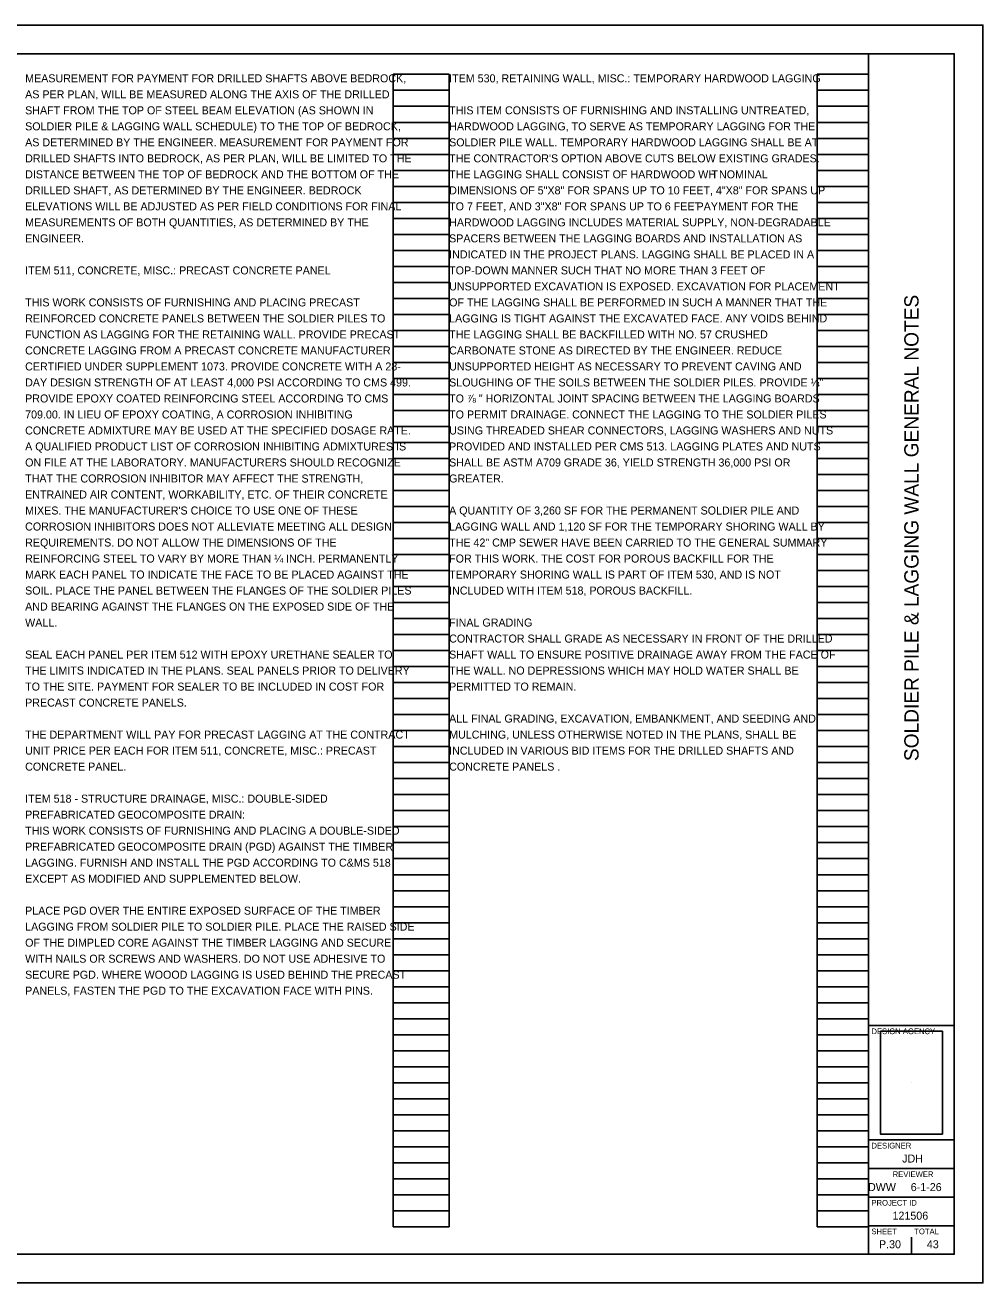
# Model space of a CAD drawing. Extents: x 0 to 34, y 0 to 22.
# Drawn here: x 17.24 to 34, y 0 to 22 of the extents above; entities that cross this region are included whole.
import ezdxf

# ---------------------------------------------------------------- set-up
doc = ezdxf.new("R2010")
doc.units = 0
for name, color, linetype in [('Default', 7, 'Continuous'), ('SH_Border', 7, 'Continuous'), ('SH_Cut_Line', 7, 'Continuous'), ('SH_Data', 7, 'Continuous'), ('SH_Text', 7, 'Continuous')]:
    doc.layers.add(name, color=color, linetype=linetype)

msp = doc.modelspace()

# ---------------------------------------------------------------- linework, layer by layer
at = {"layer": 'SH_Border'}
for p, q in [((32, 0.5), (32, 21.5)), ((32, 4.5), (33.5, 4.5)), ((32, 2.5), (33.5, 2.5)), ((32, 2), (33.5, 2)), ((32, 1.5), (33.5, 1.5)), ((32, 1), (33.5, 1))]:
    msp.add_line(p, q, dxfattribs=at)
msp.add_lwpolyline([(1.5, 21.5), (33.5, 21.5), (33.5, 0.5), (1.5, 0.5)], close=True, dxfattribs=at)
at = {"layer": 'SH_Cut_Line'}
msp.add_lwpolyline([(0, 0), (34, 0), (34, 22), (0, 22)], close=True, dxfattribs=at)
at = {"layer": 'SH_Data'}
for p, q in [((23.68, 0.98), (23.68, 21.14)), ((23.68, 21.14), (24.66, 21.14)), ((24.66, 0.98), (24.66, 21.14)), ((31.1, 0.98), (31.1, 21.14)), ((31.1, 21.14), (32, 21.14)), ((32, 0.98), (32, 21.14)), ((23.68, 20.86), (24.66, 20.86)), ((31.1, 20.86), (32, 20.86)), ((23.68, 20.58), (24.66, 20.58)), ((31.1, 20.58), (32, 20.58)), ((23.68, 20.3), (24.66, 20.3)), ((31.1, 20.3), (32, 20.3)), ((23.68, 20.02), (24.66, 20.02)), ((31.1, 20.02), (32, 20.02)), ((23.68, 19.74), (24.66, 19.74)), ((31.1, 19.74), (32, 19.74)), ((23.68, 19.46), (24.66, 19.46)), ((31.1, 19.46), (32, 19.46)), ((23.68, 19.18), (24.66, 19.18)), ((31.1, 19.18), (32, 19.18)), ((23.68, 18.9), (24.66, 18.9)), ((31.1, 18.9), (32, 18.9)), ((23.68, 18.62), (24.66, 18.62)), ((31.1, 18.62), (32, 18.62)), ((23.68, 18.34), (24.66, 18.34)), ((31.1, 18.34), (32, 18.34)), ((23.68, 18.06), (24.66, 18.06)), ((31.1, 18.06), (32, 18.06)), ((23.68, 17.78), (24.66, 17.78)), ((31.1, 17.78), (32, 17.78)), ((23.68, 17.5), (24.66, 17.5)), ((31.1, 17.5), (32, 17.5)), ((23.68, 17.22), (24.66, 17.22)), ((31.1, 17.22), (32, 17.22)), ((23.68, 16.94), (24.66, 16.94)), ((31.1, 16.94), (32, 16.94)), ((23.68, 16.66), (24.66, 16.66)), ((31.1, 16.66), (32, 16.66)), ((23.68, 16.38), (24.66, 16.38)), ((31.1, 16.38), (32, 16.38)), ((23.68, 16.1), (24.66, 16.1)), ((31.1, 16.1), (32, 16.1)), ((23.68, 15.82), (24.66, 15.82)), ((31.1, 15.82), (32, 15.82)), ((23.68, 15.54), (24.66, 15.54)), ((31.1, 15.54), (32, 15.54)), ((23.68, 15.26), (24.66, 15.26)), ((31.1, 15.26), (32, 15.26)), ((23.68, 14.98), (24.66, 14.98)), ((31.1, 14.98), (32, 14.98)), ((23.68, 14.7), (24.66, 14.7)), ((31.1, 14.7), (32, 14.7)), ((23.68, 14.42), (24.66, 14.42)), ((31.1, 14.42), (32, 14.42)), ((23.68, 14.14), (24.66, 14.14)), ((31.1, 14.14), (32, 14.14)), ((23.68, 13.86), (24.66, 13.86)), ((31.1, 13.86), (32, 13.86)), ((23.68, 13.58), (24.66, 13.58)), ((31.1, 13.58), (32, 13.58)), ((23.68, 13.3), (24.66, 13.3)), ((31.1, 13.3), (32, 13.3)), ((23.68, 13.02), (24.66, 13.02)), ((31.1, 13.02), (32, 13.02)), ((23.68, 12.74), (24.66, 12.74)), ((31.1, 12.74), (32, 12.74)), ((23.68, 12.46), (24.66, 12.46)), ((31.1, 12.46), (32, 12.46)), ((23.68, 12.18), (24.66, 12.18)), ((31.1, 12.18), (32, 12.18)), ((23.68, 11.9), (24.66, 11.9)), ((31.1, 11.9), (32, 11.9)), ((23.68, 11.62), (24.66, 11.62)), ((31.1, 11.62), (32, 11.62)), ((23.68, 11.34), (24.66, 11.34)), ((31.1, 11.34), (32, 11.34)), ((23.68, 11.06), (24.66, 11.06)), ((31.1, 11.06), (32, 11.06)), ((23.68, 10.78), (24.66, 10.78)), ((31.1, 10.78), (32, 10.78)), ((23.68, 10.5), (24.66, 10.5)), ((31.1, 10.5), (32, 10.5)), ((23.68, 10.22), (24.66, 10.22)), ((31.1, 10.22), (32, 10.22)), ((23.68, 9.94), (24.66, 9.94)), ((31.1, 9.94), (32, 9.94)), ((23.68, 9.66), (24.66, 9.66)), ((31.1, 9.66), (32, 9.66)), ((23.68, 9.38), (24.66, 9.38)), ((31.1, 9.38), (32, 9.38)), ((23.68, 9.1), (24.66, 9.1)), ((31.1, 9.1), (32, 9.1)), ((23.68, 8.82), (24.66, 8.82)), ((31.1, 8.82), (32, 8.82)), ((23.68, 8.54), (24.66, 8.54)), ((31.1, 8.54), (32, 8.54)), ((23.68, 8.26), (24.66, 8.26)), ((31.1, 8.26), (32, 8.26)), ((23.68, 7.98), (24.66, 7.98)), ((31.1, 7.98), (32, 7.98)), ((23.68, 7.7), (24.66, 7.7)), ((31.1, 7.7), (32, 7.7)), ((23.68, 7.42), (24.66, 7.42)), ((31.1, 7.42), (32, 7.42)), ((23.68, 7.14), (24.66, 7.14)), ((31.1, 7.14), (32, 7.14)), ((23.68, 6.86), (24.66, 6.86)), ((31.1, 6.86), (32, 6.86)), ((23.68, 6.58), (24.66, 6.58)), ((31.1, 6.58), (32, 6.58)), ((23.68, 6.3), (24.66, 6.3)), ((31.1, 6.3), (32, 6.3)), ((23.68, 6.02), (24.66, 6.02)), ((31.1, 6.02), (32, 6.02)), ((23.68, 5.74), (24.66, 5.74)), ((31.1, 5.74), (32, 5.74)), ((23.68, 5.46), (24.66, 5.46)), ((31.1, 5.46), (32, 5.46)), ((23.68, 5.18), (24.66, 5.18)), ((31.1, 5.18), (32, 5.18)), ((23.68, 4.9), (24.66, 4.9)), ((31.1, 4.9), (32, 4.9)), ((23.68, 4.62), (24.66, 4.62)), ((31.1, 4.62), (32, 4.62)), ((23.68, 4.34), (24.66, 4.34)), ((31.1, 4.34), (32, 4.34)), ((23.68, 4.06), (24.66, 4.06)), ((31.1, 4.06), (32, 4.06)), ((23.68, 3.78), (24.66, 3.78)), ((31.1, 3.78), (32, 3.78)), ((23.68, 3.5), (24.66, 3.5)), ((31.1, 3.5), (32, 3.5)), ((32.75, 3.5), (32.75, 3.5)), ((23.68, 3.22), (24.66, 3.22)), ((31.1, 3.22), (32, 3.22)), ((23.68, 2.94), (24.66, 2.94)), ((31.1, 2.94), (32, 2.94)), ((23.68, 2.66), (24.66, 2.66)), ((31.1, 2.66), (32, 2.66)), ((23.68, 2.38), (24.66, 2.38)), ((31.1, 2.38), (32, 2.38)), ((23.68, 2.1), (24.66, 2.1)), ((31.1, 2.1), (32, 2.1)), ((23.68, 1.82), (24.66, 1.82)), ((31.1, 1.82), (32, 1.82)), ((23.68, 1.54), (24.66, 1.54)), ((31.1, 1.54), (32, 1.54)), ((23.68, 1.26), (24.66, 1.26)), ((31.1, 1.26), (32, 1.26)), ((23.68, 0.98), (24.66, 0.98)), ((31.1, 0.98), (32, 0.98)), ((32.375, 0.675), (32.375, 0.675)), ((32.75, 0.5), (32.75, 0.8))]:
    msp.add_line(p, q, dxfattribs=at)
at = {"layer": 'SH_Text'}
msp.add_lwpolyline([(33.291, 2.599), (33.291, 4.401), (32.209, 4.401), (32.209, 2.599)], close=True, dxfattribs=at)

# ---------------------------------------------------------------- texts
at = {"layer": 'Default'}
for s, p in [('MEASUREMENT FOR PAYMENT FOR DRILLED SHAFTS ABOVE BEDROCK, ', (17.24, 21)), ('ITEM 530, RETAINING WALL, MISC.: TEMPORARY HARDWOOD LAGGING', (24.66, 21)), ('AS PER PLAN, WILL BE MEASURED ALONG THE AXIS OF THE DRILLED ', (17.24, 20.72)), ('SHAFT FROM THE TOP OF STEEL BEAM ELEVATION (AS SHOWN IN ', (17.24, 20.44)), ('THIS ITEM CONSISTS OF FURNISHING AND INSTALLING UNTREATED, ', (24.66, 20.44)), ('SOLDIER PILE & LAGGING WALL SCHEDULE) TO THE TOP OF BEDROCK, ', (17.24, 20.16)), ('HARDWOOD LAGGING, TO SERVE AS TEMPORARY LAGGING FOR THE ', (24.66, 20.16)), ('AS DETERMINED BY THE ENGINEER. MEASUREMENT FOR PAYMENT FOR ', (17.24, 19.88)), ('SOLDIER PILE WALL. TEMPORARY HARDWOOD LAGGING SHALL BE AT ', (24.66, 19.88)), ('DRILLED SHAFTS INTO BEDROCK, AS PER PLAN, WILL BE LIMITED TO THE ', (17.24, 19.6)), ("THE CONTRACTOR'S OPTION ABOVE CUTS BELOW EXISTING GRADES. ", (24.66, 19.6)), ('DISTANCE BETWEEN THE TOP OF BEDROCK AND THE BOTTOM OF THE ', (17.24, 19.32)), ('THE LAGGING SHALL CONSIST OF HARDWOOD WIT', (24.66, 19.32)), ('H NOMINAL ', (29.196, 19.32)), ('DRILLED SHAFT, AS DETERMINED BY THE ENGINEER. BEDROCK ', (17.24, 19.04)), ('DIMENSIONS OF 5"X8" FOR SPANS UP TO 10 FEET, 4"X8" FOR SPANS UP ', (24.66, 19.04)), ('ELEVATIONS WILL BE ADJUSTED AS PER FIELD CONDITIONS FOR FINAL ', (17.24, 18.76)), ('TO 7 FEET, AND 3"X8" FOR SPANS UP TO 6 FEET', (24.66, 18.76)), ('. PAYMENT FOR THE ', (28.886, 18.76)), ('MEASUREMENTS OF BOTH QUANTITIES, AS DETERMINED BY THE ', (17.24, 18.48)), ('HARDWOOD LAGGING INCLUDES MATERIAL SUPPLY, NON-DEGRADABLE ', (24.66, 18.48)), ('ENGINEER.', (17.24, 18.2)), ('SPACERS BETWEEN THE LAGGING BOARDS AND INSTALLATION AS ', (24.66, 18.2)), ('INDICATED IN THE PROJECT PLANS. LAGGING SHALL BE PLACED IN A ', (24.66, 17.92)), ('ITEM 511, CONCRETE, MISC.: PRECAST CONCRETE PANEL', (17.24, 17.64)), ('TOP-DOWN MANNER SUCH THAT NO MORE THAN 3 FEET OF ', (24.66, 17.64)), ('UNSUPPORTED EXCAVATION IS EXPOSED. EXCAVATION FOR PLACEMENT ', (24.66, 17.36)), ('THIS WORK CONSISTS OF FURNISHING AND PLACING PRECAST ', (17.24, 17.08)), ('OF THE LAGGING SHALL BE PERFORMED IN SUCH A MANNER THAT THE ', (24.66, 17.08)), ('REINFORCED CONCRETE PANELS BETWEEN THE SOLDIER PILES TO ', (17.24, 16.8)), ('LAGGING IS TIGHT AGAINST THE EXCAVATED FACE. ANY VOIDS BEHIND ', (24.66, 16.8)), ('FUNCTION AS LAGGING FOR THE RETAINING WALL. PROVIDE PRECAST ', (17.24, 16.52)), ('THE LAGGING SHALL BE BACKFILLED WITH NO. 57 CRUSHED ', (24.66, 16.52)), ('CONCRETE LAGGING FROM A PRECAST CONCRETE MANUFACTURER ', (17.24, 16.24)), ('CARBONATE STONE AS DIRECTED BY THE ENGINEER. REDUCE ', (24.66, 16.24)), ('CERTIFIED UNDER SUPPLEMENT 1073. PROVIDE CONCRETE WITH A 28-', (17.24, 15.96)), ('UNSUPPORTED HEIGHT AS NECESSARY TO PREVENT CAVING AND ', (24.66, 15.96)), ('DAY DESIGN STRENGTH OF AT LEAST 4,000 PSI ACCORDING TO CMS 499. ', (17.24, 15.68)), ('SLOUGHING OF THE SOILS BETWEEN THE SOLDIER PILES. PROVIDE ¼" ', (24.66, 15.68)), ('PROVIDE EPOXY COATED REINFORCING STEEL ACCORDING TO CMS ', (17.24, 15.4)), ('TO ⅞ " HORIZONTAL JOINT SPACING BETWEEN THE LAGGING BOARDS ', (24.66, 15.4)), ('709.00. IN LIEU OF EPOXY COATING, A CORROSION INHIBITING ', (17.24, 15.12)), ('TO PERMIT DRAINAGE. CONNECT THE LAGGING TO THE SOLDIER PILES ', (24.66, 15.12)), ('CONCRETE ADMIXTURE MAY BE USED AT THE SPECIFIED DOSAGE RATE. ', (17.24, 14.84)), ('USING THREADED SHEAR CONNECTORS, LAGGING WASHERS AND NUTS ', (24.66, 14.84)), ('A QUALIFIED PRODUCT LIST OF CORROSION INHIBITING ADMIXTURES IS ', (17.24, 14.56)), ('PROVIDED AND INSTALLED PER CMS 513. LAGGING PLATES AND NUTS ', (24.66, 14.56)), ('ON FILE AT THE LABORATORY. MANUFACTURERS SHOULD RECOGNIZE ', (17.24, 14.28)), ('SHALL BE ASTM A709 GRADE 36, YIELD STRENGTH 36,000 PSI OR ', (24.66, 14.28)), ('THAT THE CORROSION INHIBITOR MAY AFFECT THE STRENGTH, ', (17.24, 14)), ('GREATER.', (24.66, 14)), ('ENTRAINED AIR CONTENT, WORKABILITY, ETC. OF THEIR CONCRETE ', (17.24, 13.72)), ("MIXES. THE MANUFACTURER'S CHOICE TO USE ONE OF THESE ", (17.24, 13.44)), ('A QUANTITY OF 3,260 SF FOR THE PERMANENT SOLDIER PILE AND ', (24.66, 13.44)), ('CORROSION INHIBITORS DOES NOT ALLEVIATE MEETING ALL DESIGN ', (17.24, 13.16)), ('LAGGING WALL AND 1,120 SF FOR THE TEMPORARY SHORING WALL BY ', (24.66, 13.16)), ('REQUIREMENTS. DO NOT ALLOW THE DIMENSIONS OF THE ', (17.24, 12.88)), ('THE 42" CMP SEWER HAVE BEEN CARRIED TO THE GENERAL SUMMARY ', (24.66, 12.88)), ('REINFORCING STEEL TO VARY BY MORE THAN ¼ INCH. PERMANENTLY ', (17.24, 12.6)), ('FOR THIS WORK. THE COST FOR POROUS BACKFILL FOR THE ', (24.66, 12.6)), ('MARK EACH PANEL TO INDICATE THE FACE TO BE PLACED AGAINST THE ', (17.24, 12.32)), ('TEMPORARY SHORING WALL IS PART OF ITEM 530, AND IS NOT ', (24.66, 12.32)), ('SOIL. PLACE THE PANEL BETWEEN THE FLANGES OF THE SOLDIER PILES ', (17.24, 12.04)), ('INCLUDED WITH ITEM 518, POROUS BACKFILL.', (24.66, 12.04)), ('AND BEARING AGAINST THE FLANGES ON THE EXPOSED SIDE OF THE ', (17.24, 11.76)), ('WALL.', (17.24, 11.48)), ('FINAL GRADING', (24.66, 11.48)), ('CONTRACTOR SHALL GRADE AS NECESSARY IN FRONT OF THE DRILLED ', (24.66, 11.2)), ('SEAL EACH PANEL PER ITEM 512 WITH EPOXY URETHANE SEALER TO ', (17.24, 10.92)), ('SHAFT WALL TO ENSURE POSITIVE DRAINAGE AWAY FROM THE FACE OF ', (24.66, 10.92)), ('THE LIMITS INDICATED IN THE PLANS. SEAL PANELS PRIOR TO DELIVERY ', (17.24, 10.64)), ('THE WALL. NO DEPRESSIONS WHICH MAY HOLD WATER SHALL BE ', (24.66, 10.64)), ('TO THE SITE. PAYMENT FOR SEALER TO BE INCLUDED IN COST FOR ', (17.24, 10.36)), ('PERMITTED TO REMAIN.', (24.66, 10.36)), ('PRECAST CONCRETE PANELS.', (17.24, 10.08)), ('ALL FINAL GRADING, EXCAVATION, EMBANKMENT, AND SEEDING AND ', (24.66, 9.8)), ('THE DEPARTMENT WILL PAY FOR PRECAST LAGGING AT THE CONTRACT ', (17.24, 9.52)), ('MULCHING, UNLESS OTHERWISE NOTED IN THE PLANS, SHALL BE ', (24.66, 9.52)), ('UNIT PRICE PER EACH FOR ITEM 511, CONCRETE, MISC.: PRECAST ', (17.24, 9.24)), ('INCLUDED IN VARIOUS BID ITEMS FOR THE DRILLED SHAFTS AND ', (24.66, 9.24)), ('CONCRETE PANEL.', (17.24, 8.96)), ('CONCRETE PANELS .', (24.66, 8.96)), ('ITEM 518 - STRUCTURE DRAINAGE, MISC.: DOUBLE-SIDED ', (17.24, 8.4)), ('PREFABRICATED GEOCOMPOSITE DRAIN:', (17.24, 8.12)), ('THIS WORK CONSISTS OF FURNISHING AND PLACING A DOUBLE-SIDED ', (17.24, 7.84)), ('PREFABRICATED GEOCOMPOSITE DRAIN (PGD) AGAINST THE TIMBER ', (17.24, 7.56)), ('LAGGING. FURNISH AND INSTALL THE PGD ACCORDING TO C&MS 518 ', (17.24, 7.28)), ('EXCEPT AS MODIFIED AND SUPPLEMENTED BELOW. ', (17.24, 7)), ('PLACE PGD OVER THE ENTIRE EXPOSED SURFACE OF THE TIMBER ', (17.24, 6.44)), ('LAGGING FROM SOLDIER PILE TO SOLDIER PILE. PLACE THE RAISED SIDE ', (17.24, 6.16)), ('OF THE DIMPLED CORE AGAINST THE TIMBER LAGGING AND SECURE ', (17.24, 5.88)), ('WITH NAILS OR SCREWS AND WASHERS. DO NOT USE ADHESIVE TO ', (17.24, 5.6)), ('SECURE PGD. WHERE WOOOD LAGGING IS USED BEHIND THE PRECAST ', (17.24, 5.32)), ('PANELS, FASTEN THE PGD TO THE EXCAVATION FACE WITH PINS.', (17.24, 5.04))]:
    msp.add_text(s, height=0.14, dxfattribs=at).set_placement(p)
at = {"layer": 'SH_Data'}
msp.add_text('SOLDIER PILE & LAGGING WALL GENERAL NOTES', height=0.25, rotation=90, dxfattribs=at).set_placement((32.875, 9.127))
for s, height, p in [('DESIGN AGENCY', 0.1, (32.05, 4.35)), ('DESIGNER', 0.1, (32.05, 2.35)), ('JDH', 0.14, (32.588, 2.105)), ('REVIEWER', 0.1, (32.422, 1.85)), ('DWW', 0.14, (31.99, 1.605)), ('6-1-26', 0.14, (32.738, 1.605)), ('PROJECT ID', 0.1, (32.05, 1.35)), ('121506', 0.14, (32.419, 1.105)), ('SHEET', 0.1, (32.05, 0.85)), ('TOTAL', 0.1, (32.8, 0.85)), ('P.30', 0.14, (32.182, 0.605)), ('43', 0.14, (33.02, 0.605))]:
    msp.add_text(s, height=height, dxfattribs=at).set_placement(p)

doc.saveas('drawing.dxf')
